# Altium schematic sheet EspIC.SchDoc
size A4; CheckedBy: Everyone how cares; DocumentNumber: 4; SheetNumber: 4; SheetTotal: 4
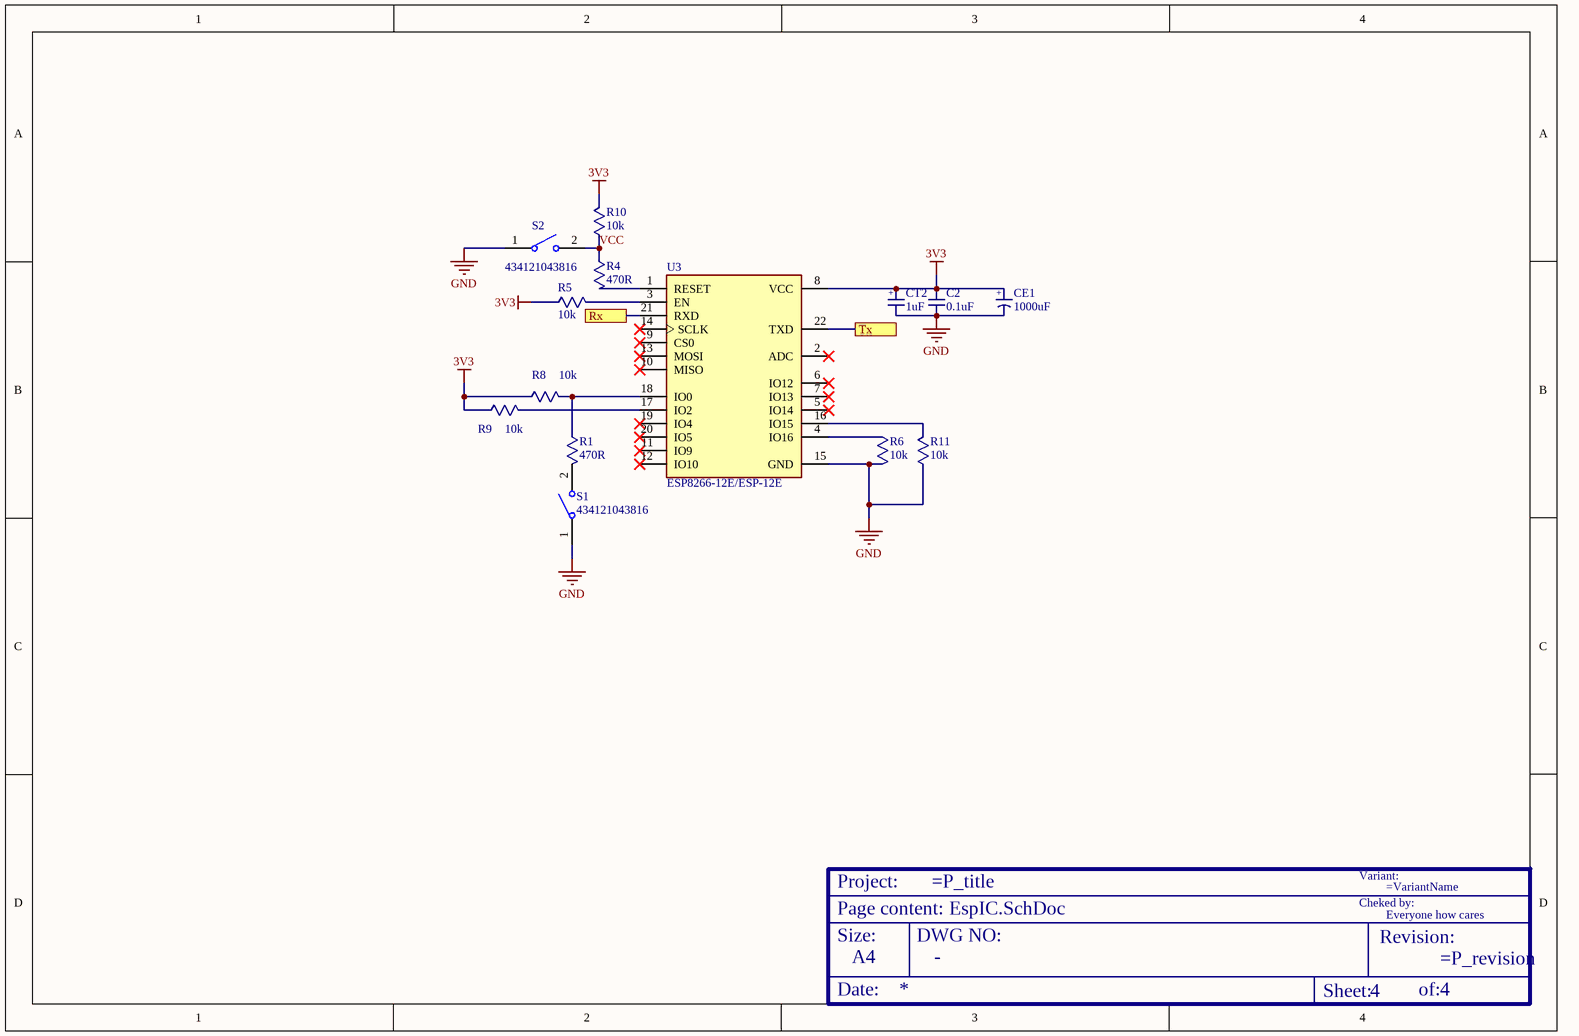
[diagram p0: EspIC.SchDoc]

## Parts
?  Size: A4  (hidden comment: TitleBox)  (graphical)
C2  value 0.1uF  [0603C]  (hidden comment: Ceramic Capacitor)
CE1  value 1000uF  [WCAP-AS5H_8x10.5]  (hidden comment: Eletrolitic Capacitor)
CT2  value 1uF  [0603T]  (hidden comment: Tantalum capacitor)
R1  value 470R  [0603]  (hidden comment: Res)
R4  value 470R  [0603]  (hidden comment: Res)
R5  value 10k  [0603]  (hidden comment: Res)
R6  value 10k  [0603]  (hidden comment: Res)
R8  value 10k  [0603]  (hidden comment: Res)
R9  value 10k  [0603]  (hidden comment: Res)
R10  value 10k  [0603]  (hidden comment: Res)
R11  value 10k  [0603]  (hidden comment: Res)
S1  value 434121043816  [434121043816]  (hidden comment: Swich)
S2  value 434121043816  [434121043816]  (hidden comment: Swich)
U3  ESP8266-12E/ESP-12E  [XCVR_ESP8266-12E/ESP-12E]

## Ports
Rx, Tx

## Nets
3V3: C2.1 CE1.1 CT2.1 R5.1 R8.1 R9.1 R10.2 U3.8(VCC)
GND: C2.2 CE1.2 CT2.2 R6.2 R11.1 S1.1 S2.1 U3.15(GND)
Rx: U3.21(RXD) ; port Rx
Tx: U3.22(TXD) ; port Tx
VCC: R4.1 R10.1 S2.2
NetR1_1: R1.1 R8.2 U3.18(IO0)
NetR1_2: R1.2 S1.2
NetR4_2: R4.2 U3.1(RESET)
NetR5_2: R5.2 U3.3(EN)
NetR6_1: R6.1 U3.4(IO16)
NetR9_2: R9.2 U3.17(IO2)
NetR11_2: R11.2 U3.16(IO15)

Not connected (* = marked no-connect by the designer): U3 2(ADC)* 5(IO14)* 6(IO12)* 7(IO13)* 9(CS0)* 10(MISO)* 11(IO9)* 12(IO10)* 13(MOSI)* 14(SCLK)* 19(IO4)* 20(IO5)*

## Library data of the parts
? = TitleBox_1: coordenadas: (610;20) Size A4
C2 = CC
CE1 = CE: notas: MCVVT6R3M102FB3L
CT2 = CT: Condensador Tantalum; notas: TMCJ1C105MTRF
S1 S2 = switch 2 patas smd: 6x3.5mm SMD WS-TASV, height 4.3 mm, 160 gf
U3 = ESP8266-12E/ESP-12E: This WiFi module has a 32-bit MCU micro and clock speeds supporting 80 MHz or 160 MHz. Supports the RTOS and integrated Wi-Fi MAC/BB/RF/PA/LNA, and has an on-board antenna.; MF: AI-Thinker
